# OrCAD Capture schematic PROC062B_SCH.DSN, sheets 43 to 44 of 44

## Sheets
43 43. OVER VOLTAGE PROTECTION CKT: size C; title: OVER VOLTAGE  PROTECTION CKT AND TEST AUTOMATION POWER
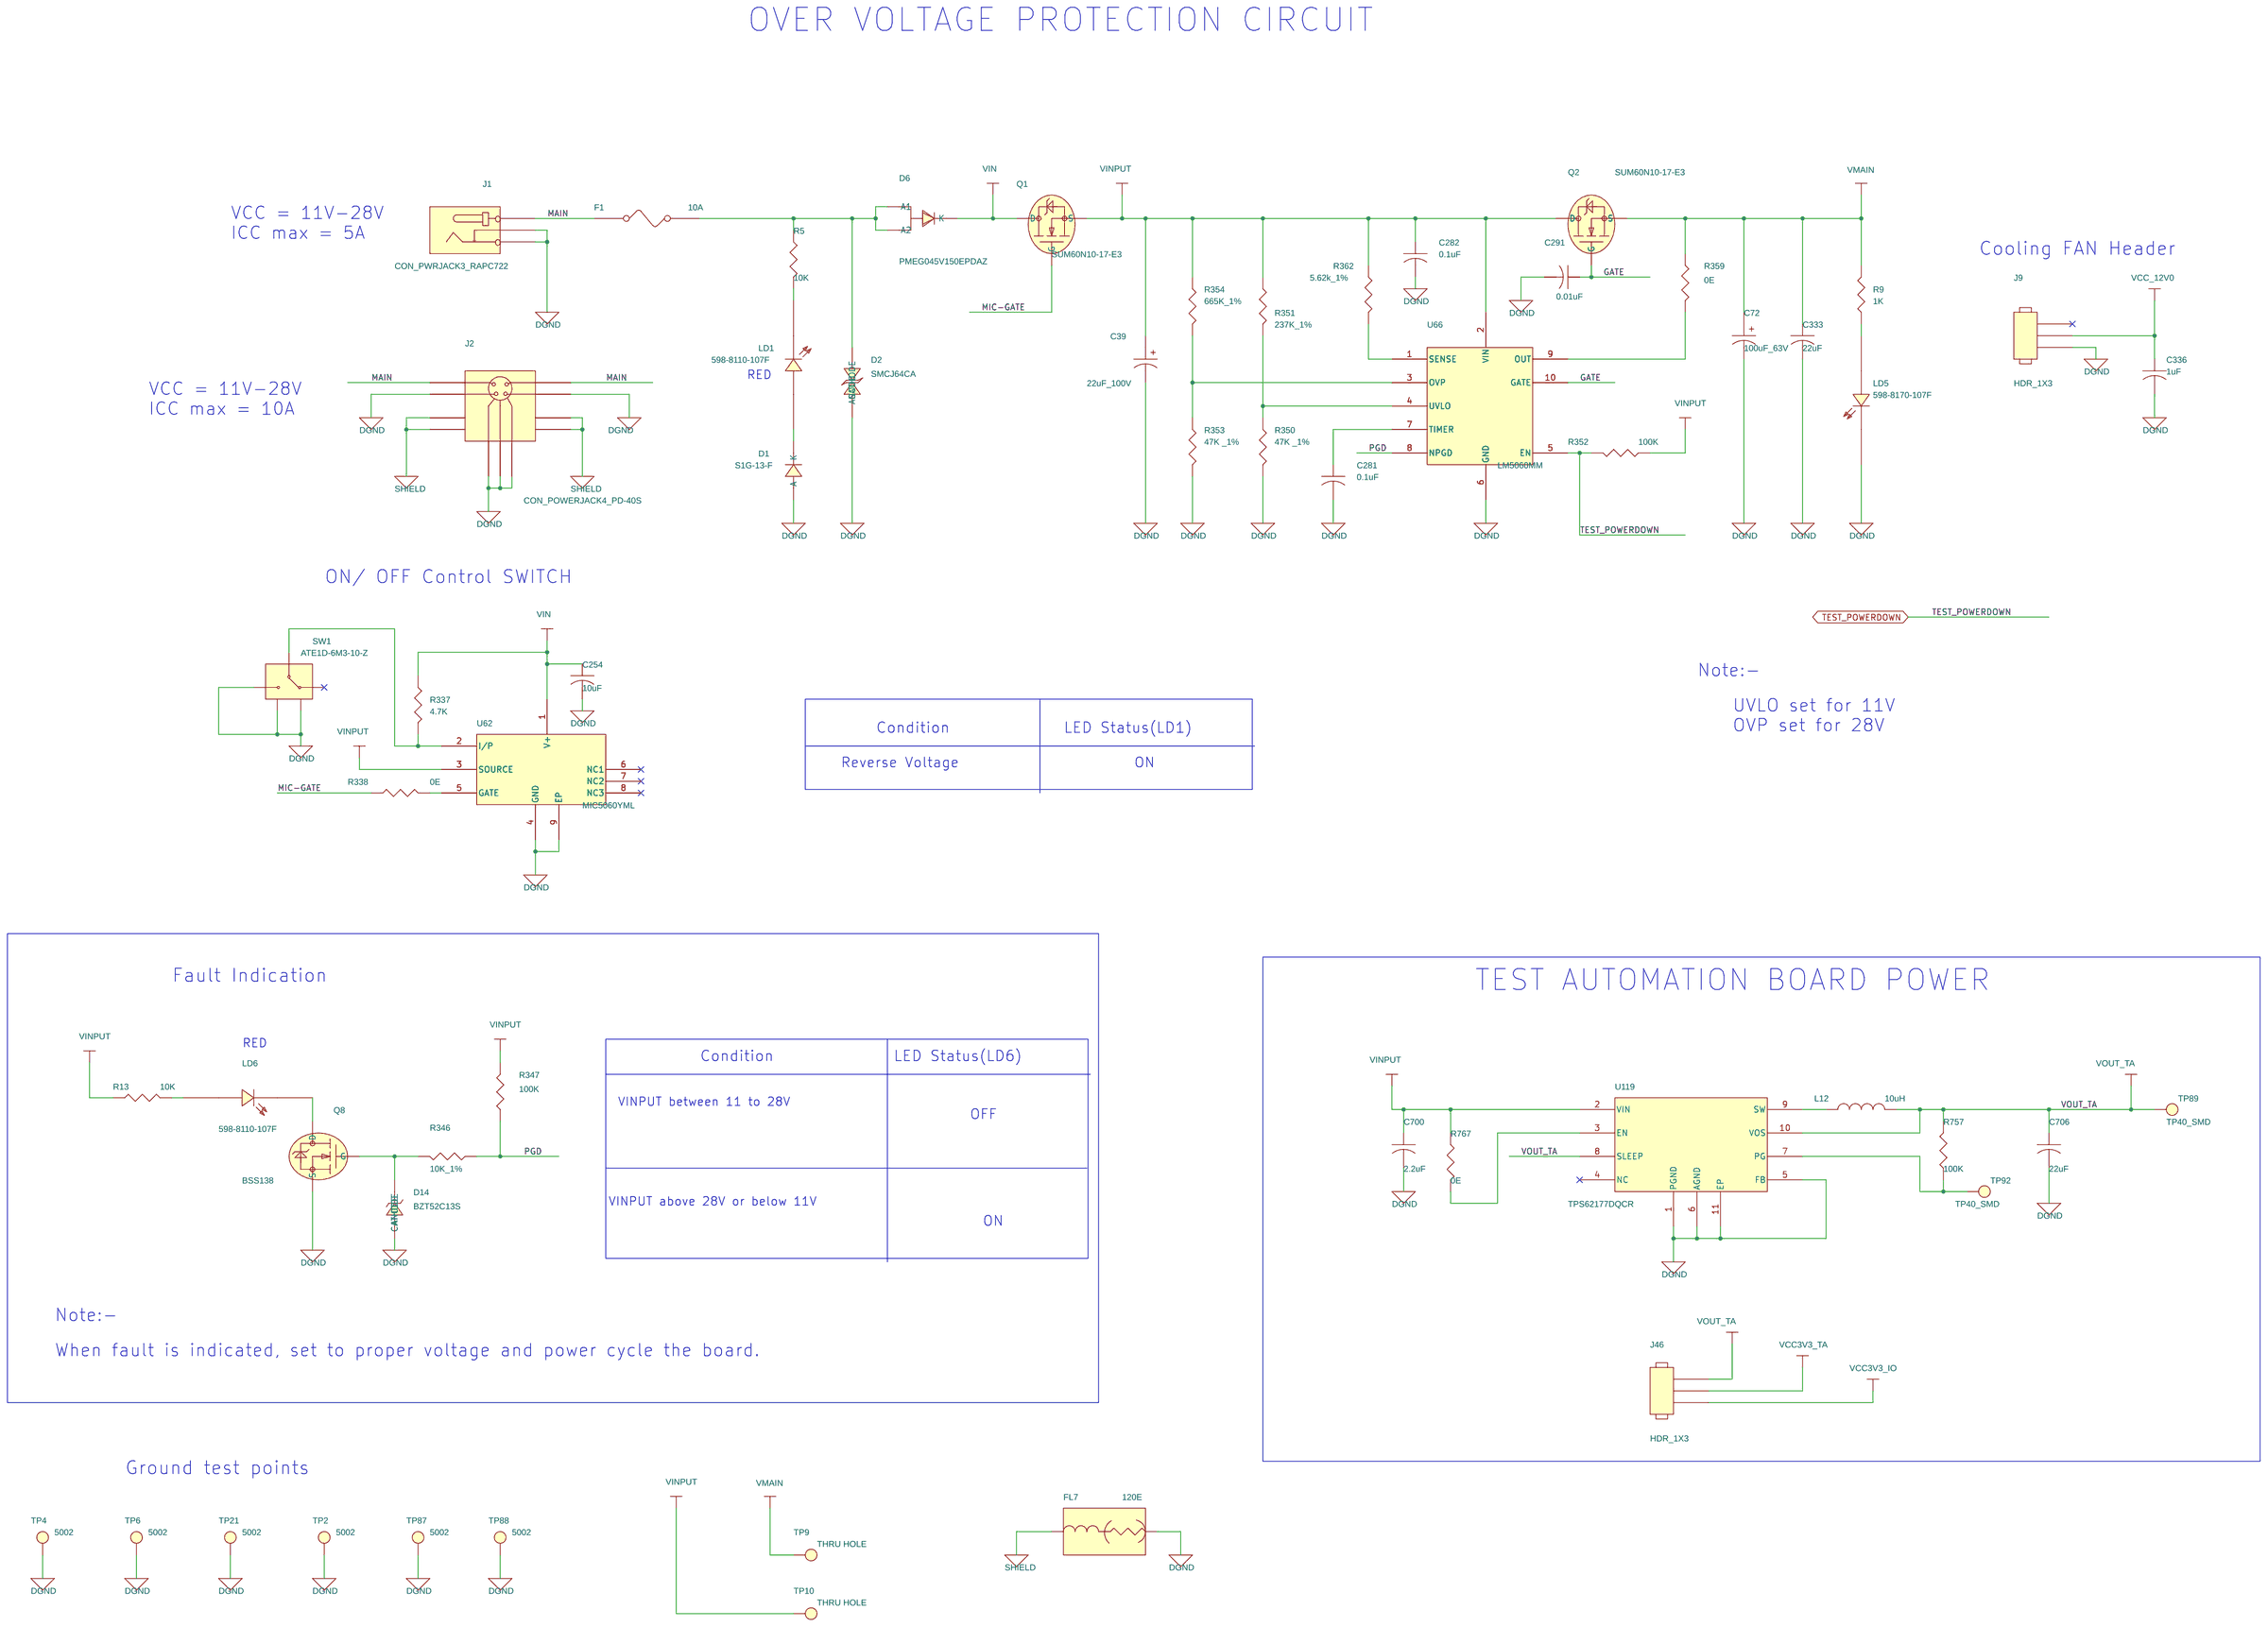
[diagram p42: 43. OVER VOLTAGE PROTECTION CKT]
44 35. CSI,GPMC/DSS INTERFACE: size C; title: CSI,GPMC/DSS INTERFACE
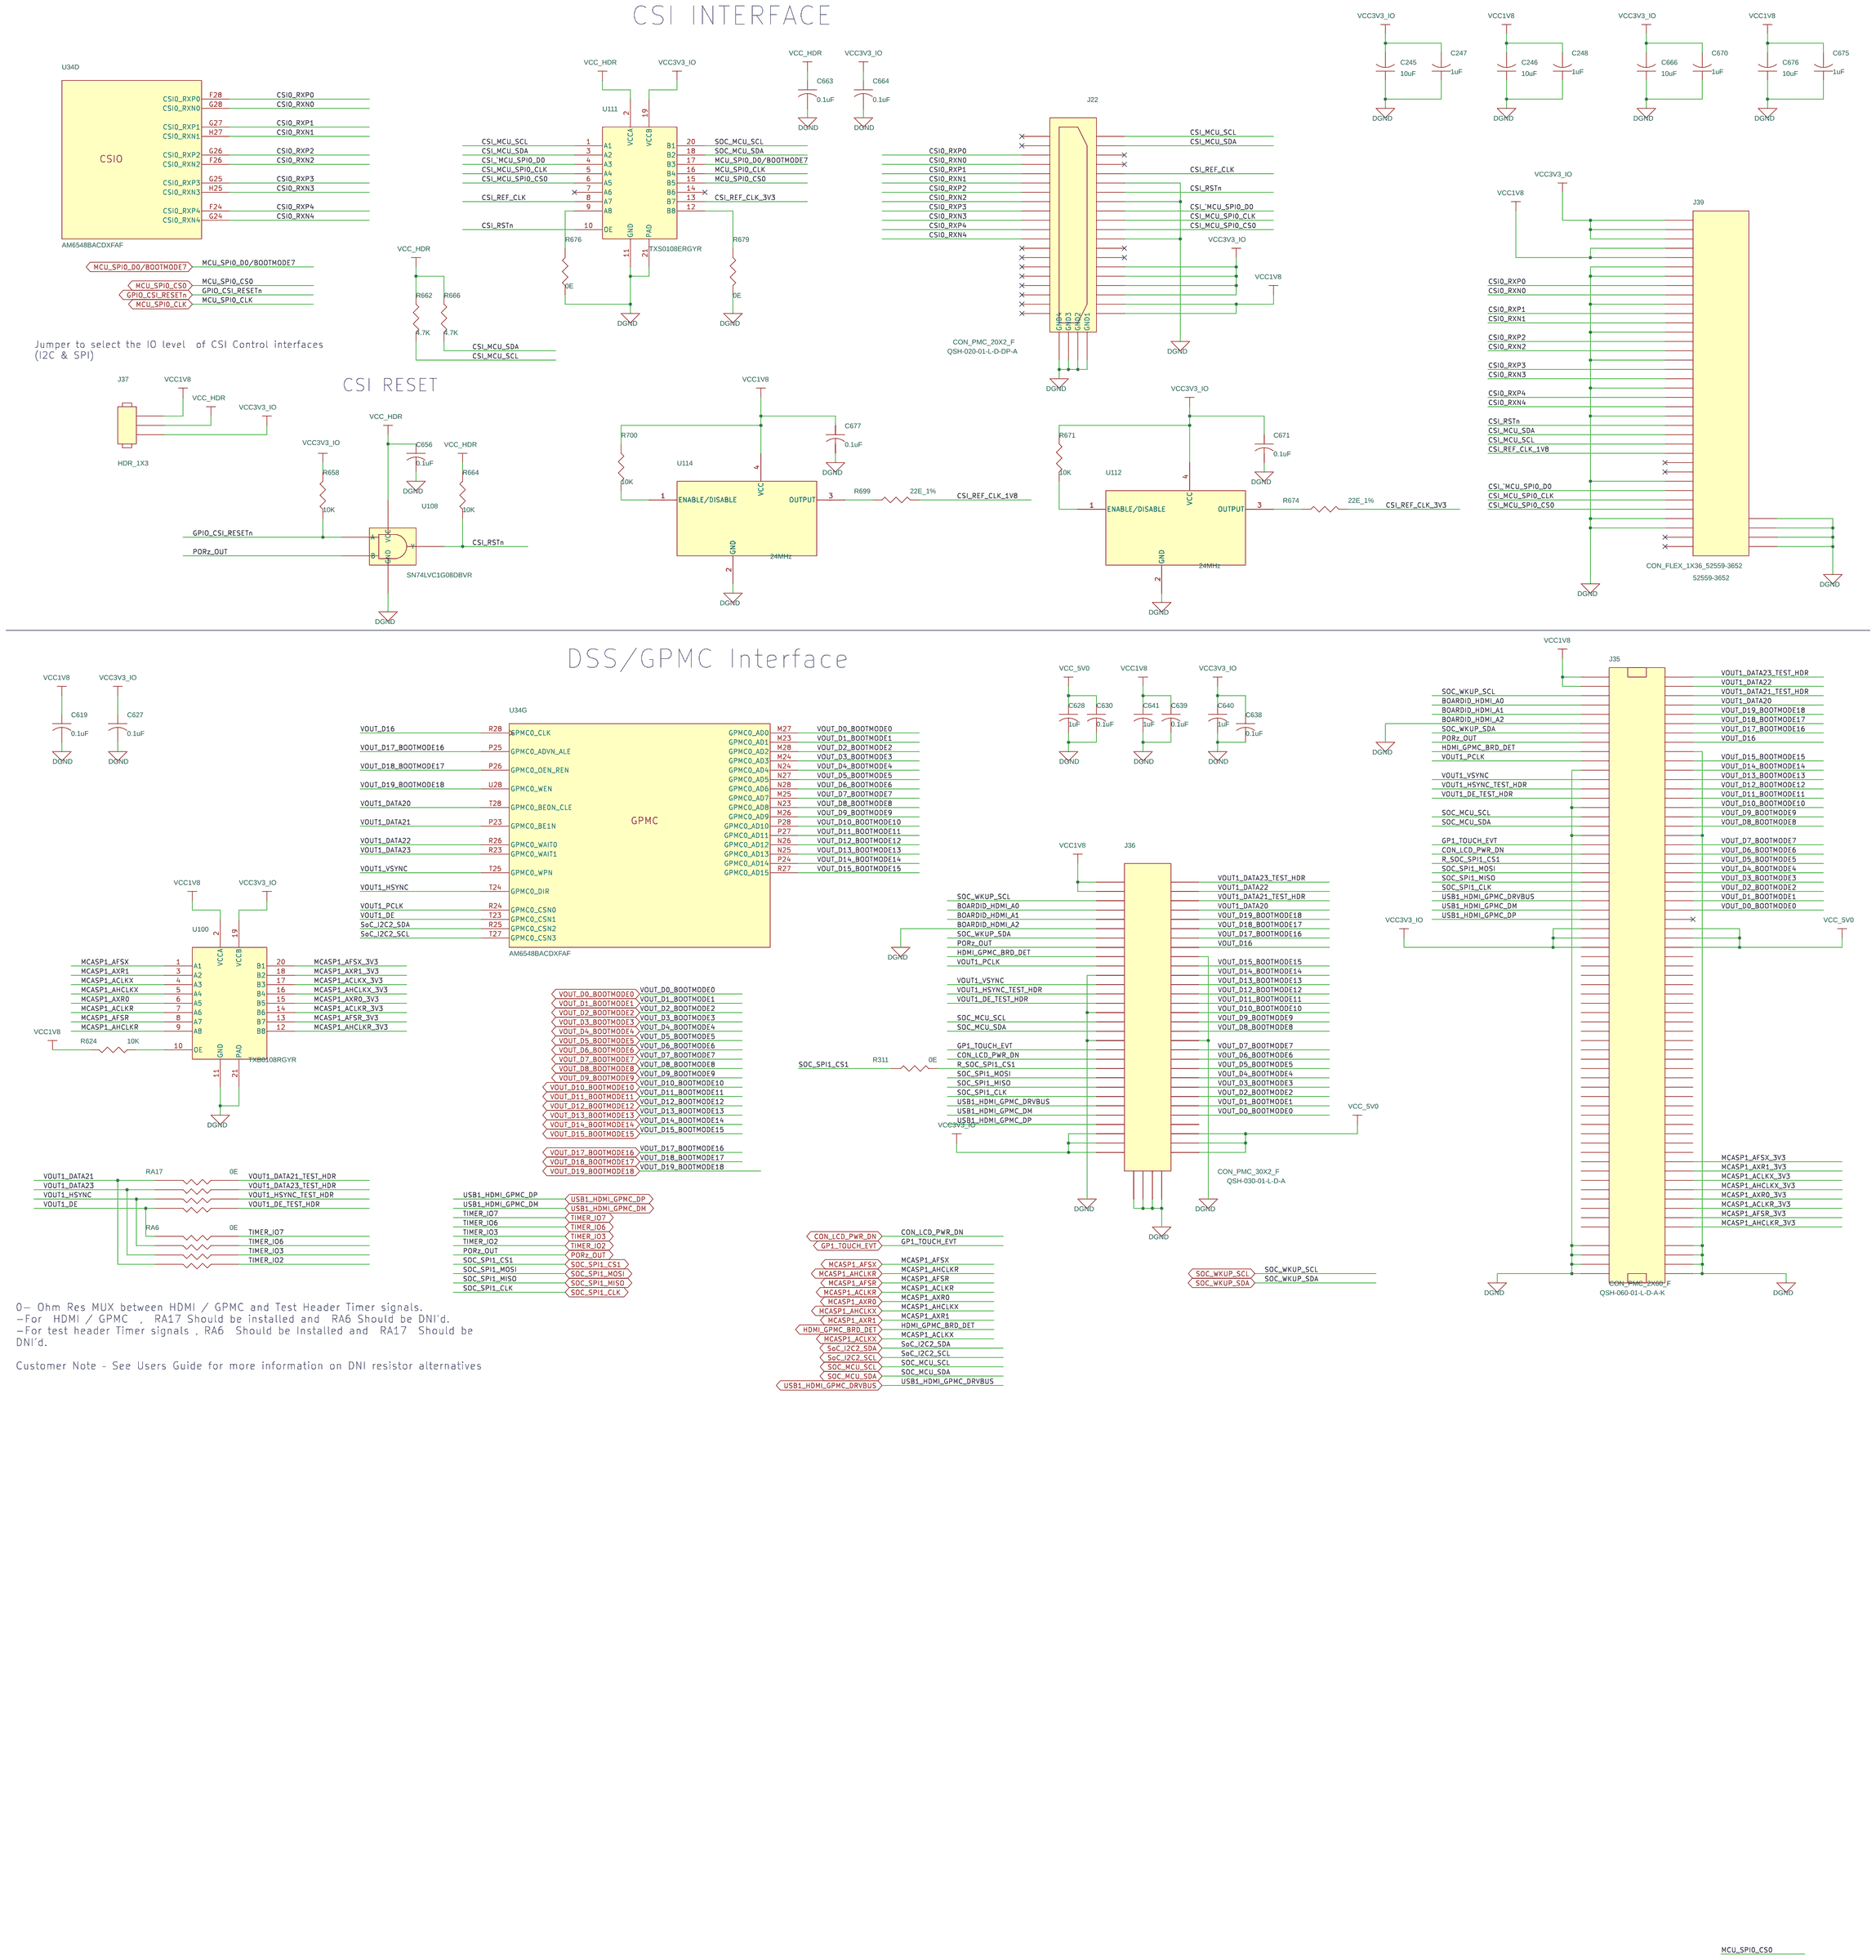
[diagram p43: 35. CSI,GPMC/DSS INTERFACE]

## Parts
sheet 16. DDR4 ECC & TERMINATIONS
U34  AM6548BACDXFAF  [BGA784_31-49_910X910_1-7]  (sections A,B,C,D,E,F,G,H,I,J,K,L,M,N,O,P,Q,R,S)
sheet 35. CSI,GPMC/DSS INTERFACE
C245  10uF  [CAP0603_1]
C246  10uF  [CAP0603_1]
C247  1uF  [CAP0402_0-75]
C248  1uF  [CAP0402_0-75]
C619  0.1uF  [CAP0201_0-5]
C627  0.1uF  [CAP0201_0-5]
C628  1uF  [CAP0402_0-75]
C630  0.1uF  [CAP0201_0-5]
C638  0.1uF  [CAP0201_0-5]
C639  0.1uF  [CAP0201_0-5]
C640  1uF  [CAP0402_0-75]
C641  1uF  [CAP0402_0-75]
C656  0.1uF  [CAP0201_0-5]
C663  0.1uF  [CAP0201_0-5]
C664  0.1uF  [CAP0201_0-5]
C666  10uF  [CAP0603_1]
C670  1uF  [CAP0402_0-75]
C671  0.1uF  [CAP0201_0-5]
C675  1uF  [CAP0402_0-75]
C676  10uF  [CAP0603_1]
C677  0.1uF  [CAP0201_0-5]
J22  CON_PMC_20X2_F  [CON_PMC20X2_QSH-D-DP_S_S_S]
J35  CON_PMC_2X60_F  [CON_PMC60X2_HQCD-060_S_S_S_3-3]
J36  CON_PMC_30X2_F  [CON_PMC30X2_QSH-030-01-L_S_S_S]
J37  HDR_1X3  [HDR_3X1_100_S_T]
J39  CON_FLEX_1X36_52559-3652  [CON_FLEX1X36_52559-36_S_S_S_5-3]
R311  0E  [RES0402_0-5]
R624  10K  [RES0402_0-5]
R658  10K  [RES0402_0-5]
R662  4.7K  [RES0402]
R664  10K  [RES0402_0-5]
R666  4.7K  [RES0402]
R671  10K  [RES0402_0-5]
R674  22E_1%  [RES0402]
R676  0E  [RES0402_0-5]
R679  0E  [RES0402_0-5]
R699  22E_1%  [RES0402]
R700  10K  [RES0402_0-5]
RA6  0E  [RESA_EXBN8V_0402-4_0-6]
RA17  0E  [RESA_EXBN8V_0402-4_0-6]
U100  TXB0108RGYR  [QFN20_19-68_185X145_1]
U108  SN74LVC1G08DBVR  [SOT23-5]
U111  TXS0108ERGYR  [QFN20_19-68_185X145_1]
U112  24MHz  [OSC4_KC2520B_100X80_SMD]
U114  24MHz  [OSC4_KC2520B_100X80_SMD]
sheet 43. OVER VOLTAGE PROTECTION CKT
C39  22uF_100V  [CAPAE_GCASE]
C72  100uF_63V  [CAPAE_CASE103103_11]
C254  10uF  [CAP1206_2]
C281  0.1uF  [CAP0603_1]
C282  0.1uF  [CAP0603_1]
C291  0.01uF  [CAP0201_0-5]
C333  22uF  [CAP7563_4]
C336  1uF  [CAP0603_1]
C700  2.2uF  [CAP1206_2]
C706  22uF  [CAP1206_2]
D1  S1G-13-F  [DIO_SMA]
D2  SMCJ64CA  [DIO_SMC]
D6  PMEG045V150EPDAZ  [CFP15_PMEG045V150EPD_0-9]
D14  BZT52C13S  [DIO_SOD323]
F1  10A  [FUSE_397_410X110_SMD_2-9]
FL7  120E  [EMIFIL_BLM15A_0402_0-6]
J1  CON_PWRJACK3_RAPC722  [CON_PWRJACK3_RAPC722_P_R_T]
J2  CON_POWERJACK4_PD-40S  [CON_POWERJACK4_PD-40S_S_R_T_15]
J9  HDR_1X3  [HDR_1X3_440054-3_S_T_6-4]
J46  HDR_1X3  [HDR_3X1_100_S_T]
L12  10uH  [IND_LPS4018-MR_160X160_SMD_1-8]
LD1  598-8110-107F  [LED_0805]
LD5  598-8170-107F  [LED_0805_0-7]
LD6  598-8110-107F  [LED_0805]
Q1  SUM60N10-17-E3  [D2PAK-3]
Q2  SUM60N10-17-E3  [D2PAK-3]
Q8  BSS138  [TO_SOT23-123]
R5  10K  [RES1206]
R9  1K  [RES0201]
R13  10K  [RES1206]
R337  4.7K  [RES0402]
R338  0E  [RES0402_0-5]
R346  10K_1%  [RES0402_0-5]
R347  100K  [RES0402_0-5]
R350  47K _1%  [RES0402_0-5]
R351  237K_1%  [RES0402]
R352  100K  [RES0402_0-5]
R353  47K _1%  [RES0402_0-5]
R354  665K_1%  [RES0603_0-5]
R359  0E  [RES0402_0-5]
R362  5.62k_1%  [RES0603]
R757  100K  [RES0402_0-5]
R767  0E  [RES0402_0-5]
SW1  ATE1D-6M3-10-Z  [SW3_ATE1F-6M3_370X710_TH_5-6]
TP2  5002  [TP_CIR67D40_TH_4-6]
TP4  5002  [TP_CIR67D40_TH_4-6]
TP6  5002  [TP_CIR67D40_TH_4-6]
TP9  THRU HOLE  [TP_40X65]
TP10  THRU HOLE  [TP_40X65]
TP21  5002  [TP_CIR67D40_TH_4-6]
TP87  5002  [TP_CIR67D40_TH_4-6]
TP88  5002  [TP_CIR67D40_TH_4-6]
TP89  TP40_SMD  [TP40_SMD]
TP92  TP40_SMD  [TP40_SMD]
U62  MIC5060YML  [DFN8_25-59_120X120_1]
U66  LM5060MM  [MSOP10_19-68_120X120]
U119  TPS62177DQCR  [WSON10_19-68_80X120_0-8]

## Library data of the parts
U34 = AM654X_BGA784: IC AM65X MICRO CONTROLLER UNIT BGA784; Chkd/date: ALVY/010721; Crtd /date: MANIRAJA/010721; Custom_Duty: 15%; Customs_HS_Code: 85423100; Distributor_name: NA; Distributor_part_number: NA; Footprint Path: Y:\MIS_DATABASE\Library\ALTIUM_TOOL\PCB_FOOTPRINTS\Altium_Footprint_Lib.PcbLib; Height: 1.63MM; Library Path: Y:\MIS_DATABASE\Library\ALTIUM_TOOL\SCHEMATICS_PARTS\MS_MICROCONTROLLER_Library.schlib; Mfr_name: TEXAS INSTRUMENTS; Mistral Part No: 141221070001; Package: BGA784; Part_type: ICS\DIGITAL\MICROCONTROLLER; Project: TI_AM65X_CP; RoHS: NA; Temperature: NA; Tolerance: NA; Voltage: NA; Wattage: NA; Weight: NA; Datasheet: Y:\MIS_DATABASE\DATASHEETS\ICS\DIGITAL\MICROCONTROLLER\MAXWELLM4.PDF
C245 C246 C666 C676 = CAP: CAP CERAMIC 10uF 10V 10% X5R 0603; Chkd/date: MANIRAJA/230118; Crtd /date: MANIRAJA/230118; Custom_Duty: 15%; Customs_HS_Code: 85322990; Distributor_name: DIGIKEY; Distributor_part_number: 478-10766-1-ND; Height: 0.94MM; Mfr_name: AVX CORPORATION; Mfr_part_number: 0603ZD106KAT2A; Mistral Part No: 120010080001-R; Package: 0603; Part_type: CAPACITORS\CERAMIC; Project: TI_MAXIE_CPB; RoHS: RoHS; Temperature: -55°C+85°C; Tolerance: 10%; Voltage: 10V; Wattage: NA; Weight: 2mg; Datasheet: Y:\MIS_DATABASE\DATASHEETS\CAPACITORS\AVX_MLC.PDF
C247 C248 C628 C640 C641 C670 C675 = CAP: CAP CERAMIC 1uF 16V 20% X5R 0402; Chkd/date: MANIRAJA/150218; Crtd /date: ALVY/150218; Custom_Duty: 15%; Customs_HS_Code: 85322990; Distributor_name: DIGIKEY; Distributor_part_number: 587-5514-1-ND; Footprint Path: Y:\MIS_DATABASE\Library\ALTIUM_TOOL\PCB_FOOTPRINTS\Altium_Footprint_Lib.PcbLib; Height: 0.55MM; Library Path: Y:\MIS_DATABASE\Library\ALTIUM_TOOL\SCHEMATICS_PARTS\MS_DISCRETE_Library.schlib; Mfr_name: TAIYO YUDEN; Mfr_part_number: EMK105BJ105MV-F; Mistral Part No: 120018020006-R; Package: 0402; Part_type: CAPACITORS\CERAMIC; Project: TI_MAXIE_CPB; RoHS: RoHS; Temperature: -55°C+85°C; Tolerance: 20%; Voltage: 16V; Wattage: NA; Weight: 0.65mg; Datasheet: Y:\MIS_DATABASE\DATASHEETS\CAPACITORS\EMK105BJ105MV-F.PDF
C619 C627 C630 C638 C639 C656 C663 C664 C671 C677 = CAP: CAP CERAMIC 0.1uF 16V 10% X5R 0201; Chkd/date: MANIRAJA/120218; Crtd /date: MANIRAJA/120218; Custom_Duty: 15%; Customs_HS_Code: 85322990; Distributor_name: DIGIKEY; Distributor_part_number: 490-16742-1-ND; Height: 0.33MM; Mfr_name: MURATA; Mfr_part_number: GRM033R61C104KE84J; Mistral Part No: 120009030072-R; Package: 0201; Part_type: CAPACITORS\CERAMIC; Project: TI_MAXIE_CPB; RoHS: RoHS; Temperature: -55°C+85°C; Tolerance: 10%; Voltage: 16V; Wattage: NA; Weight: 0.33mg; Datasheet: Y:\MIS_DATABASE\DATASHEETS\CAPACITORS\GRM033R61C104KE84.PDF
J22 = CON_PMC_20X2_F: CON PMC 20X2 0.50MM PITCH FEMALE ST SMD; Chkd/date: USMAN/021214; Crtd /date: CHAITHANYA/031111; Custom_Duty: 24%; Customs_HS_Code: 85369090; Distributor_name: DIGIKEY; Distributor_part_number: QSH-020-01-L-D-DP-A-ND; Height: 3.25MM; Mfr_name: SAMTEC; Mfr_part_number: QSH-020-01-L-D-DP-A; Mistral Part No: 150011110006-R; Package: SMD; Part_type: CONNECTOR\PMC; Project: LLTR; RoHS: RoHS; Temperature: -55°C+125°C; Tolerance: NA; Voltage: NA; Wattage: NA; Weight: NA; Datasheet: Y:\MIS_DATABASE\DATASHEETS\CONNECTORS\QSH-SERIES.PDF
J35 = CON_PMC_60X2_HQCD: CON PMC 2X60 0.50MM PITCH FEMALE ST SMD; Chkd/date: MANIRAJA/230817; Crtd /date: MUDDU/020610; Custom_Duty: 24%; Customs_HS_Code: 85369090; Distributor_name: DIGIKEY; Distributor_part_number: SAM10652-ND; Height: 3.25MM; Mfr_name: SAMTEC; Mfr_part_number: QSH-060-01-L-D-A-K; Mistral Part No: 150010060004-R; Package: SMD; Part_type: CONNECTOR\PMC; Project: CENTAURUS; RoHS: RoHS; Temperature: -55°C+125°C; Tolerance: NA; Voltage: NA; Wattage: NA; Weight: NA; Datasheet: Y:\MIS_DATABASE\DATASHEETS\CONNECTORS\QSH.PDF
J36 = CON_PMC_30X2_F: CON PMC 30X2 0.50MM PITCH FEMALE ST SMD; Chkd/date: MAZHAR/180208; Crtd /date: USMAN/051108; Custom_Duty: 24%; Customs_HS_Code: 85369090; Height: 3.25MM; Mfr_name: SAMTEC; Mfr_part_number: QSH-030-01-L-D-A; Mistral Part No: 150009030606; Package: SMD; Part_type: CONNECTOR\PMC; Project: KHAN_HSST; Datasheet: Y:\MIS_DATABASE\DATASHEETS\CONNECTORS\QSH.PDF
J37 J46 = HEADER_3X1: HDR 1X3 2.54MM PITCH ST TH; Chkd/date: VASANTHA/290616; Crtd /date: VASANTHA/290616; Custom_Duty: 15%; Customs_HS_Code: 85322990; Distributor_name: DIGIKEY; Distributor_part_number: 609-3471-ND; Height: 8.58MM; Mfr_name: FCI; Mfr_part_number: 68001-403HLF; Mistral Part No: 150016060025-R; Package: THRU-HOLE; Part_type: CONNECTOR\HEADERS; Project: IKEYP; RoHS: RoHS; Temperature: -40°C+105°C; Tolerance: NA; Voltage: NA; Wattage: NA; Weight: NA; Datasheet: Y:\MIS_DATABASE\DATASHEETS\CONNECTORS\68000.PDF
J39 = CON_FLEX_36X1_52559-3652: CON FPC 1X36 0.50MM PITCH ST SMD; Chkd/date: MANIRAJA/060917; Crtd /date: MANIRAJA/060917; Custom_Duty: 24%; Customs_HS_Code: 85369090; Distributor_name: DIGIKEY; Distributor_part_number: WM7988CT-ND; Height: 5.30MM; Mfr_name: MOLEX; Mfr_part_number: 52559-3652; Mistral Part No: 150017090006-R; Package: SMD; Part_type: CONNECTOR\FPC; Project: TI_SVB_MAXWELL_DUT; RoHS: RoHS; Temperature: -40°C+85°C; Tolerance: NA; Voltage: NA; Wattage: NA; Weight: 429.23mg; Datasheet: Y:\MIS_DATABASE\DATASHEETS\CONNECTORS\52559.PDF
R311 R338 R359 R676 R679 R767 = RESISTOR: RES 0E 1/16W 0402; Chkd/date: VASANTHA/201216; Crtd /date: MUDDU/190810; Custom_Duty: 15%; Customs_HS_Code: 85332119; Distributor_name: DIGIKEY; Distributor_part_number: 541-0.0JCT-ND; Footprint Path: Y:\MIS_DATABASE\Library\ALTIUM_TOOL\PCB_FOOTPRINTS\Altium_Footprint_Lib.PcbLib; Height: 0.40MM; Library Path: Y:\MIS_DATABASE\Library\ALTIUM_TOOL\SCHEMATICS_PARTS\MS_DISCRETE_Library.schlib; Mfr_name: VISHAY; Mfr_part_number: CRCW04020000Z0ED; Mistral Part No: 110010080019-P; Package: 0402; Part_type: RESISTORS\FIXED; Project: PB_BUGBASE; RoHS: Pb-Free; Temperature: -55°C+155°C; Tolerance: NA; Voltage: NA; Wattage: 1/16W; Weight: 0.65g/1000pcs; Datasheet: Y:\MIS_DATABASE\DATASHEETS\RESISTORS\CRCW0603.PDF
R624 R658 R664 R671 R700 = RESISTOR: RES 10K 1/16W 5% 0402; Chkd/date: VASANTHA/061216; Crtd /date: MAZHAR/230805; Custom_Duty: 15%; Customs_HS_Code: 85332119; Distributor_name: DIGIKEY; Distributor_part_number: 311-10KJRCT-ND; Footprint Path: Y:\MIS_DATABASE\Library\ALTIUM_TOOL\PCB_FOOTPRINTS\Altium_Footprint_Lib.PcbLib; Height: 0.40MM; Library Path: Y:\MIS_DATABASE\Library\ALTIUM_TOOL\SCHEMATICS_PARTS\MS_DISCRETE_Library.schlib; Mfr_name: YAGEO AMERICA; Mfr_part_number: RC0402JR-0710KL; Mistral Part No: 110009030208-R; Package: 0402; Part_type: RESISTORS\FIXED; Project: HSE; RoHS: Pb-Free; Temperature: -55°C+155°C; Tolerance: 5%; Voltage: NA; Wattage: 1/16W; Weight: 0.65mg; Datasheet: Y:\MIS_DATABASE\DATASHEETS\RESISTORS\YAGEO-RC0402.PDF
R337 R662 R666 = RESISTOR: RES 4.7K 1/16W 5% 0402; Chkd/date: VASANTHA/130516; Crtd /date: VASANTHA/130516; Custom_Duty: 15%; Customs_HS_Code: 85332119; Distributor_name: DIGIKEY; Distributor_part_number: 311-4.7KJRCT-ND; Height: 0.55MM; Mfr_name: YAGEO AMERICA; Mfr_part_number: RC0402JR-074K7L; Mistral Part No: 110009030792-R; Package: 0402; Part_type: RESISTORS\FIXED; Project: TMDXCSK368; RoHS: RoHS; Temperature: -55°C+155°C; Tolerance: 5%; Voltage: NA; Wattage: 1/16W; Weight: NA; Datasheet: Y:\MIS_DATABASE\DATASHEETS\RESISTORS\YAGEO-RC0402.PDF
R674 R699 = RESISTOR: RES 22E 1/16W 1% 0402; Alternate_mfr_name_A: VISHAY; Alternate_mfr_part_number_A: CRCW040222R0FKED; Chkd/date: SUHAS/290910; Crtd /date: MAZHAR/090909; Cust_part_number: 4700-80047E; Custom_Duty: 15%; Customs_HS_Code: 85332119; Distributor_name: DIGIKEY; Distributor_name_A: DIGIKEY; Distributor_part_number: 311-22.0LRCT-ND; Distributor_part_number_A: 541-22.0LCT-ND; Height: 0.40MM; Mfr_name: YAGEO AMERICA; Mfr_part_number: RC0402FR-0722RL; Mistral Part No: 110009090004-P; Package: 0402; Part_type: RESISTORS\FIXED; Project: VMEFMCD; Remarks: In alternate datasheet it is RoHS COMPLIANT. Y:\MIS_DATABASE\DATASHEETS\RESISTORS\CRCW0402.PDF; RoHS: Pb-Free; SIGNAL_MODEL: RESISTOR_RES0402_22E_22E; Temperature: -55°C+155°C; Tolerance: 1%; Voltage: 50V; Wattage: 1/16W; Weight: 0.8g/1000pcs; Datasheet: Y:\MIS_DATABASE\DATASHEETS\RESISTORS\YAGEO-RC0402.PDF
RA6 RA17 = RESARR_ISO4: RES ARRAY 0E 31mW 0402-4; Chkd/date: MANIRAJA/161017; Crtd /date: USMAN/190209; Distributor_name: DIGIKEY; Distributor_part_number: Y10000CT-ND; Height: 0.55MM; Mfr_name: PANASONIC-ECG; Mfr_part_number: EXB-N8VR000X; Mistral Part No: 110009030002-R; Package: 0402-4; Part_type: RESISTORS\ARRAY; Project: AXON; RoHS: RoHS; Temperature: -55°C+125°C; Tolerance: NA; Voltage: NA; Wattage: 31mW; Weight: 3mg; Datasheet: Y:\MIS_DATABASE\DATASHEETS\RESISTORS\EXB-X.PDF
U100 = TXB0108RGYR_VQFN20: IC 8-BIT TRANSLATOR 15KV ESD VQFN20; Chkd/date: VASANTHA/221216; Crtd /date: MUDDU/190510; Custom_Duty: 15%; Customs_HS_Code: 85423100; Distributor_name: DIGIKEY; Distributor_part_number: 296-21528-1-ND; Height: 1.00MM; Mfr_name: TEXAS INSTRUMENTS; Mistral Part No: 141010050005-R; Package: VQFN20; Part_type: ICS\INTERFACE; Project: SHIVA; RoHS: Sb/ Br FREE; Temperature: -40°C+85°C; Tolerance: NA; Voltage: NA; Wattage: NA; Weight: 43mg; Datasheet: Y:\MIS_DATABASE\DATASHEETS\ICS\INTERFACE\TXB0108RGYR.PDF
U108 = SN74LVC1G08DBVR_SOT23-5: IC SINGLE 2-INPUT POSITIVE AND GATE SOT23-5; Chkd/date: SHREESHAIL/270906; Crtd /date: MAZHAR/270906; Custom_Duty: 15%; Customs_HS_Code: 85423100; Distributor_name: DIGIKEY; Distributor_part_number: 296-11601-1-ND; Height: 1.45MM; Mfr_name: TEXAS INSTRUMENTS; Mistral Part No: 141009030228-R; Part_type: ICS\DIGITAL\GATES; Project: SVDO_RMB_MMA; RoHS: Sb/ Br FREE; Datasheet: Y:\MIS_DATABASE\DATASHEETS\ICS\DIGITAL\GATES\SN74LVC1G08.PDF
U111 = TXS0108ERGYR_QFN20: IC TRANSLATOR BIDIRECTIONAL VOLTAGE-LEVEL 8BIT QFN20; Chkd/date: VASANTHA/060117; Crtd /date: BAVISH/280411; Custom_Duty: 15%; Customs_HS_Code: 85423100; Distributor_name: DIGIKEY; Distributor_part_number: 296-24806-1-ND; Height: 1.00MM; Mfr_name: TEXAS INSTRUMENTS; Mistral Part No: 141011040019-R; Package: QFN20; Part_type: ICS\INTERFACE; Project: OMAPL1_PEC20; RoHS: RoHS; Temperature: -40°C+85°C; Tolerance: NA; Voltage: NA; Wattage: NA; Weight: 43mg; Datasheet: Y:\MIS_DATABASE\DATASHEETS\ICS\INTERFACE\TXS0108E.PDF
U112 U114 = OSC_KC2520B: OSC 24MHz 1.8V SMD; Chkd/date: NAVEED/080415; Crtd /date: JEBRAN/310315; Custom_Duty: 24%; Customs_HS_Code: 85437099; Distributor_name: DIGIKEY; Distributor_part_number: 1253-1244-1-ND; Height: 0.70MM; Mfr_name: KYOCERA; Mfr_part_number: KC2520B24.0000C1GE00; Mistral Part No: 130015030022-R; Package: SMD; Part_type: OSCILLATORS; Project: DLRL; RoHS: RoHS; Temperature: -40°C+85°C; Tolerance: NA; Voltage: NA; Wattage: NA; Weight: NA; Datasheet: Y:\MIS_DATABASE\DATASHEETS\MISC\CRY_OSC\KC2520B2.PDF
C39 = CAP_POL: CAP ELECTROLYTIC 22uF 100V 20% GCASE_103103; Chkd/date: USMAN/141211; Crtd /date: CHAITHANYA/131211; Custom_Duty: 15%; Customs_HS_Code: 85322990; Distributor_name: DIGIKEY; Distributor_part_number: PCE4250CT-ND; Height: 10.50MM; Mfr_name: PANASONIC-ECG; Mfr_part_number: EEE-HA2A220P; Mistral Part No: 120011120008-R; Package: GCASE_103103; Part_type: CAPACITORS\ELECTROLYTIC; Project: NA10NG; RoHS: RoHS; Temperature: -40°C+105°C; Tolerance: 20%; Voltage: 100V; Wattage: NA; Weight: NA; Datasheet: Y:\MIS_DATABASE\DATASHEETS\CAPACITORS\EEEHA-V-SERIES.PDF
C72 = CAP_POL: CAP ELECTROLYTIC 100uF 63V 20% CASE_103103; Chkd/date: MANIRAJA/120218; Crtd /date: MANIRAJA/120218; Custom_Duty: 15%; Customs_HS_Code: 85322990; Distributor_name: DIGIKEY; Distributor_part_number: 493-7453-1-ND; Height: 10.80MM; Mfr_name: NICHICON; Mfr_part_number: UUX1J101MNL1GS; Mistral Part No: 120018010018-R; Package: CASE_103103; Part_type: CAPACITORS\ELECTROLYTIC; Project: TI_MAXIE_CPB; RoHS: RoHS; Temperature: -55°C+105°C; Tolerance: 20%; Voltage: 63V; Wattage: NA; Weight: 1.21g; Datasheet: Y:\MIS_DATABASE\DATASHEETS\CAPACITORS\UUX-SER.PDF
C254 = CAP: CAP CERAMIC 10uF 50V 10% X5R 1206; Chkd/date: VASANTHA/190814; Crtd /date: BAVISH/230611; Custom_Duty: 15%; Customs_HS_Code: 85322990; Distributor_name: DIGIKEY; Distributor_part_number: 445-5998-1-ND; Footprint Path: Y:\MIS_DATABASE\Library\ALTIUM_TOOL\PCB_FOOTPRINTS\Altium_Footprint_Lib.PcbLib; Height: 1.90MM; Library Path: Y:\MIS_DATABASE\Library\ALTIUM_TOOL\SCHEMATICS_PARTS\MS_DISCRETE_Library.schlib; Mfr_name: TDK CORPORATION; Mfr_part_number: C3216X5R1H106K160AB; Mistral Part No: 120016030005-R; Package: 1206; Part_type: CAPACITORS\CERAMIC; Project: ITS-SINGAL_COND_CARD; RoHS: RoHS; Temperature: -55°C+85°C; Tolerance: 10%; Voltage: 50V; Wattage: NA; Weight: 16.2mg; Datasheet: Y:\MIS_DATABASE\DATASHEETS\CAPACITORS\TDK_C-SER-JUL17.PDF
C281 C282 = CAP: CAP CERAMIC 0.1uF 50V 20% X7R 0603; Chkd/date: MANIRAJA/240118; Crtd /date: MANIRAJA/240118; Custom_Duty: 15%; Customs_HS_Code: 85322990; Distributor_name: DIGIKEY; Distributor_part_number: 399-7845-1-ND; Height: 0.95MM; Mfr_name: KEMET; Mfr_part_number: C0603C104M5RACTU; Mistral Part No: 120018010021-R; Package: 0603; Part_type: CAPACITORS\CERAMIC; Project: TI_MAXIE_CPB; RoHS: RoHS; Temperature: -55°C+125°C; Tolerance: 20%; Voltage: 50V; Wattage: NA; Weight: 2mg; Datasheet: Y:\MIS_DATABASE\DATASHEETS\CAPACITORS\KEMET-X7R-SER.PDF
C291 = CAP: CAP CERAMIC 0.01uF 25V 10% X5R 0201; Chkd/date: MANIRAJA/230118; Crtd /date: MANIRAJA/230118; Custom_Duty: 15%; Customs_HS_Code: 85322990; Distributor_name: DIGIKEY; Distributor_part_number: GRM033R61E103KA12J-ND; Height: 0.33MM; Mfr_name: MURATA; Mfr_part_number: GRM033R61E103KA12J; Mistral Part No: 120018010007-R; Package: 0201; Part_type: CAPACITORS\CERAMIC; Project: TI_MAXIE_CPB; RoHS: RoHS; Temperature: -55°C+85°C; Tolerance: 10%; Voltage: 25V; Wattage: NA; Weight: 0.33mg; Datasheet: Y:\MIS_DATABASE\DATASHEETS\CAPACITORS\GRM033R61E103KA12.PDF
C333 = CAP: CAP CERAMIC 22uF 50V 20% X7R 7563; Chkd/date: MANIRAJA/121017; Crtd /date: MANIRAJA/121017; Custom_Duty: 15%; Customs_HS_Code: 85322990; Distributor_name: DIGIKEY; Distributor_part_number: 565-4700-1-ND; Height: 4.00MM; Mfr_name: NIPPON CHEMICON; Mfr_part_number: KTS500B226M76N0T00; Mistral Part No: 120017100007-R; Package: 7563; Part_type: CAPACITORS\CERAMIC; Project: TI_MAXIE_CPB; RoHS: RoHS; Temperature: -55°C+125°C; Tolerance: 20%; Voltage: 50V; Wattage: NA; Weight: NA; Datasheet: Y:\MIS_DATABASE\DATASHEETS\CAPACITORS\NTS-NTF-SER.PDF
C336 = CAP: CAP CERAMIC 1uF 25V 10% X5R 0603; Chkd/date: MANIRAJA/230118; Crtd /date: MANIRAJA/230118; Custom_Duty: 15%; Customs_HS_Code: 85322990; Distributor_name: DIGIKEY; Distributor_part_number: 478-5142-1-ND; Height: 0.94MM; Mfr_name: AVX CORPORATION; Mfr_part_number: 06033D105KAT2A; Mistral Part No: 120010080040-R; Package: 0603; Part_type: CAPACITORS\CERAMIC; Project: TI_MAXIE_CPB; RoHS: RoHS; Temperature: -55°C+85°C; Tolerance: 10%; Voltage: 25V; Wattage: NA; Weight: 2mg; Datasheet: Y:\MIS_DATABASE\DATASHEETS\CAPACITORS\AVX_MLC.PDF
C700 = CAP: CAP CERAMIC 2.2uF 50V 10% X7R AUTO 1206; Chkd/date: MAZHAR/290208; Crtd /date: USMAN/280208; Custom_Duty: 15%; Customs_HS_Code: 85322990; Distributor_name: DIGIKEY; Distributor_part_number: 490-4796-1-ND; Footprint Path: Y:\MIS_DATABASE\Library\ALTIUM_TOOL\PCB_FOOTPRINTS\Altium_Footprint_Lib.PcbLib; Height: 1.80MM; Library Path: Y:\MIS_DATABASE\Library\ALTIUM_TOOL\SCHEMATICS_PARTS\MS_DISCRETE_Library.schlib; Mfr_name: MURATA; Mfr_part_number: GCM31CR71H225KA55L; Mistral Part No: 120009030284-R; Package: 1206; Part_type: CAPACITORS\CERAMIC; Project: HS100RD; RoHS: RoHS; Temperature: -55°C+125°C; Tolerance: 10%; Voltage: 50V; Wattage: NA; Weight: 52mg; Datasheet: Y:\MIS_DATABASE\DATASHEETS\CAPACITORS\GCM31CR71H225KA55X.PDF
C706 = CAP: CAP CERAMIC 22uF 16V 20% X7R 1206; Chkd/date: VASANTHA/170117; Crtd /date: VASANTHA/170117; Custom_Duty: 15%; Customs_HS_Code: 85322990; Distributor_name: DIGIKEY; Distributor_part_number: 587-4319-1-ND; Height: 1.90MM; Mfr_name: TAIYO YUDEN; Mfr_part_number: EMK316BB7226ML-T; Mistral Part No: 120017010003-R; Package: 1206; Part_type: CAPACITORS\CERAMIC; Project: TRMM_SMART-M_PS; RoHS: RoHS; Temperature: -55°C+125°C; Tolerance: 20%; Voltage: 16V; Wattage: NA; Weight: 16.2mg; Datasheet: Y:\MIS_DATABASE\DATASHEETS\CAPACITORS\EMK316BB7226ML.PDF
D1 = DIODE: DIODE RECTIFIER 400V 1A SMA; Chkd/date: SUHAS/061010; Crtd /date: USMAN/220808; Custom_Duty: 15%; Customs_HS_Code: 85412900; Distributor_name: DIGIKEY; Distributor_part_number: S1G-FDICT-ND; Height: 2.30MM; Mfr_name: DIODES INC; Mistral Part No: 130009030153; Package: SMA; Part_type: DIODE\RECTIFIER; Project: CPB; Temperature: -65°C+150°C; Voltage: 400V; Weight: 0.0064g; Datasheet: Y:\MIS_DATABASE\DATASHEETS\DISCRETES\DIODES\S1.PDF
D2 = DIODE_TVS_DUAL: DIODE TVS BI-DIE 1500W 64V SMC; Chkd/date: VASANTHA/101015; Crtd /date: VASANTHA/101015; Custom_Duty: 15%; Customs_HS_Code: 85412900; Distributor_name: DIGIKEY; Distributor_part_number: SMCJ64CALFCT-ND; Height: 2.62MM; Mfr_name: LITTLE FUSE; Mistral Part No: 130015100009-R; Package: SMC; Part_type: DIODE\TVS; Project: GALILEO_EVM; RoHS: RoHS; Temperature: -55°C+150°C; Tolerance: NA; Voltage: 64V; Wattage: NA; Weight: NA; Datasheet: Y:\MIS_DATABASE\DATASHEETS\DISCRETES\DIODES\LTFUSE-SMCJ.PDF
D6 = DIODE_SCHOTTKY_POWERMITE-3: DIODE SCHOTTKY RECTIFIER 45V 15A CFP15 (SOT1289); Chkd/date: MANIRAJA/070220; Crtd /date: ALVY/070220; Custom_Duty: 15%; Customs_HS_Code: 85412900; Distributor_name: DIGIKEY; Distributor_part_number: 1727-1905-1-ND; Footprint Path: Y:\MIS_DATABASE\Library\ALTIUM_TOOL\PCB_FOOTPRINTS\Altium_Footprint_Lib.PcbLib; Height: 0.82MM; Library Path: Y:\MIS_DATABASE\Library\ALTIUM_TOOL\SCHEMATICS_PARTS\MS_DISCRETE_Library.schlib; Mfr_name: NEXPERIA; Mistral Part No: 130020020003-R; Package: CFP15; Part_type: DIODE\SCHOTTKY; Project: TI_MAXIE_CPB; RoHS: RoHS; Temperature: -55°C+175°C; Tolerance: NA; Voltage: NA; Wattage: NA; Weight: 87.3mg; Datasheet: Y:\MIS_DATABASE\DATASHEETS\DISCRETES\DIODES\PMEG045V150EPD.PDF
D14 = DIODE_ZENER: DIODE ZENER 13V 200mW SOD323; Chkd/date: MAZHAR/101210; Crtd /date: BAVISH/101210; Custom_Duty: 15%; Customs_HS_Code: 85412900; Distributor_name: DIGIKEY; Distributor_part_number: BZT52C13S-FDICT-ND; Height: 1.05MM; Mfr_name: DIODES INC; Mfr_part_number: BZT52C13S-7-F; Mistral Part No: 130010120013-R; Package: SOD323; Part_type: DIODE\ZENER; Project: IEMS; RoHS: RoHS; Temperature: -65°C+150°C; Tolerance: NA; Voltage: NA; Wattage: 200mW; Weight: 0.004g; Datasheet: Y:\MIS_DATABASE\DATASHEETS\DISCRETES\DIODES\BZT52C.PDF
F1 = FUSE: FUSE 10A 60V FAST SMD; Chkd/date: RAGESH/151010; Crtd /date: MAZHAR/220907; Distributor_name: DIGIKEY; Distributor_part_number: TR2/1025FA10-R-ND; Height: 2.90MM; Mfr_name: COOPER BUSSMANN; Mfr_part_number: 1025FA10-R; Mistral Part No: 130009030821-R; Package: SMD; Part_type: MISC\FUSE; Project: SMART VIEW_NVR; RoHS: RoHS; Voltage: 60V; Datasheet: Y:\MIS_DATABASE\DATASHEETS\MISC\FUSE\1025FA-SER.PDF
FL7 = EMIFILTER_IND: FERRITE CHIP 120E 1.3A 0402; Chkd/date: VASANTHA/010117; Crtd /date: CHAITHANYA/150312; Custom_Duty: 24%; Customs_HS_Code: 85437099; Distributor_name: DIGIKEY; Distributor_part_number: 490-5203-1-ND; Footprint Path: Y:\MIS_DATABASE\Library\ALTIUM_TOOL\PCB_FOOTPRINTS\Altium_Footprint_Lib.PcbLib; Height: 0.55MM; Library Path: Y:\MIS_DATABASE\Library\ALTIUM_TOOL\SCHEMATICS_PARTS\MS_FILTER_Library.schlib; Mfr_name: MURATA; Mfr_part_number: BLM15PD121SN1; Mistral Part No: 130012030043-R; Package: 0402; Part_type: MISC\FILTER; Project: GEN_3-8; RoHS: RoHS; Temperature: -55°C+125°C; Tolerance: 25%; Voltage: NA; Wattage: NA; Weight: 0.65mg; Datasheet: Y:\MIS_DATABASE\DATASHEETS\DISCRETES\INDUCTORS\BLM18K-SERIES.PDF
J1 = CON_PWRJACK3_RAPC722: CON POWER JACK 3POS 5A 1.93MMPIN-DIA MALE RT TH; Chkd/date: MAZHAR/220311; Crtd /date: BAVISH/230211; Custom_Duty: 24%; Customs_HS_Code: 85369090; Distributor_name: DIGIKEY; Distributor_part_number: SC1313-ND; Height: 11.00MM; Mfr_name: SWITCHCRAFT; Mfr_part_number: RAPC722X; Mistral Part No: 150011020010-R; Package: THRU-HOLE; Part_type: CONNECTOR\JACK; Project: KENNEL; RoHS: RoHS; Temperature: NA; Tolerance: NA; Voltage: NA; Wattage: NA; Weight: SOIC8; Datasheet: Y:\MIS_DATABASE\DATASHEETS\CONNECTORS\RAPC722.PDF
J2 = CON_POWERJACK_PD-40S: CON POWER JACK 4POS FEMALE RT TH; Chkd/date: VASANTHA/140616; Crtd /date: VASANTHA/140616; Custom_Duty: 24%; Customs_HS_Code: 85369090; Distributor_name: DIGIKEY; Distributor_part_number: CP-7240-ND; Height: 15.00MM; Mfr_name: CUI INC; Mfr_part_number: PD-40S; Mistral Part No: 150016060015-R; Package: THRU-HOLE; Part_type: CONNECTOR\JACK; Project: NTR_GPSDO BOX CARD; RoHS: RoHS; Temperature: NA; Tolerance: NA; Voltage: NA; Wattage: NA; Weight: NA; Datasheet: Y:\MIS_DATABASE\DATASHEETS\CONNECTORS\PD-40S.PDF
J9 = HEADER_3X1: CON HDR 1X3 2.00MM PITCH ST TH; Chkd/date: MANIRAJA/261017; Crtd /date: MANIRAJA/261017; Custom_Duty: 24%; Customs_HS_Code: 85369090; Distributor_name: DIGIKEY; Distributor_part_number: A100035-ND; Height: 6.35MM; Mfr_name: TE CONNECTIVITY; Mfr_part_number: 440054-3; Mistral Part No: 150017100038-R; Package: THRU-HOLE; Part_type: CONNECTOR\HEADERS; Project: TI_MAXIE_CPB; RoHS: RoHS; Temperature: -25°C+85°C; Tolerance: NA; Voltage: NA; Wattage: NA; Weight: NA; Datasheet: Y:\MIS_DATABASE\DATASHEETS\CONNECTORS\440054XXX.PDF
L12 = INDUCTOR: IND POWER 10uH 1.25A 20% SMD; Chkd/date: MANIRAJA/190819; Crtd /date: MANIRAJA/190819; Custom_Duty: 15%; Customs_HS_Code: 85412900; Distributor_name: MOUSER; Distributor_part_number: 994-LPS4018-103MRC; Footprint Path: Y:\MIS_DATABASE\Library\ALTIUM_TOOL\PCB_FOOTPRINTS\Altium_Footprint_Lib.PcbLib; Height: 1.80MM; Library Path: Y:\MIS_DATABASE\Library\ALTIUM_TOOL\SCHEMATICS_PARTS\MS_DISCRETE_Library.schlib; Mfr_name: COILCRAFT; Mfr_part_number: LPS4018-103MRC; Mistral Part No: 130019080008-R; Package: SMD; Project: TI_J7_SVB-DUT; RoHS: RoHS; Temperature: -40°C+85°C; Tolerance: 20%; Voltage: NA; Wattage: NA; Weight: 100mg; Datasheet: Y:\MIS_DATABASE\DATASHEETS\DISCRETES\INDUCTORS\LPS4018-RB-SERIES.PDF
LD1 LD6 = LED_598-8170-107F: LED ALINGAP RED CLEAR 0805 SMD; Chkd/date: BALACHANDAR/160514; Crtd /date: SARANYA/070514; Custom_Duty: 24%; Customs_HS_Code: 85437099; Distributor_name: DIGIKEY; Distributor_part_number: 350-2038-1-ND; Height: 0.70MM; Mfr_name: DIALIGHT; Mistral Part No: 130014050069-R; Package: 0805; Part_type: OPTO\LED; Project: AEGIS GP BETA2; RoHS: RoHS; Temperature: NA; Tolerance: NA; Voltage: NA; Wattage: NA; Weight: NA; Datasheet: Y:\MIS_DATABASE\DATASHEETS\DISCRETES\LEDS\598-SER.PDF
LD5 = LED_598-8170-107F: LED ALINGAP GREEN CLEAR 0805; Chkd/date: MANIRAJA/230817; Crtd /date: SARANYA/070514; Custom_Duty: 24%; Customs_HS_Code: 85437099; Distributor_name: DIGIKEY; Distributor_part_number: 350-2044-1-ND; Height: 0.70MM; Mfr_name: DIALIGHT; Mistral Part No: 130014050065-R; Package: 0805; Part_type: OPTO\LED; Project: AEGIS GP BETA2; RoHS: RoHS; Temperature: -30°C+85°C; Tolerance: NA; Voltage: NA; Wattage: NA; Weight: NA; Datasheet: Y:\MIS_DATABASE\DATASHEETS\DISCRETES\LEDS\598-SER.PDF
Q1 Q2 = MOSFET_IRFZ24NS: IC POWER MOSFET N-CHANNEL D2PAK; Chkd/date: VASANTHA/101015; Crtd /date: VASANTHA/101015; Custom_Duty: 15%; Customs_HS_Code: 85423100; Distributor_name: DIGIKEY; Distributor_part_number: SUM60N10-17-E3CT-ND; Height: 4.82MM; Mfr_name: VISHAY; Mistral Part No: 142015100008-R; Package: D2PAK; Part_type: ICS\POWER\MOSFET; Project: GALILEO_EVM; RoHS: RoHS; Temperature: -55°C+175°C; Tolerance: NA; Voltage: 100V; Wattage: NA; Weight: NA; Datasheet: Y:\MIS_DATABASE\DATASHEETS\DISCRETES\TRANSISTORS_FETS\SUM60N10.PDF
Q8 = MOSFET_BSS138: IC MOSFET N-CHANNEL 50V 200mA SOT23-3; Chkd/date: SUHAS/191010; Crtd /date: USMAN/240709; Custom_Duty: 15%; Customs_HS_Code: 85423100; Distributor_name: DIGIKEY; Distributor_part_number: BSS138CT-ND; Height: 1.20MM; Mfr_name: DIODES INC; Mfr_part_number: BSS138-7-F; Mistral Part No: 142009070019-R; Package: SOT23-3; Part_type: ICS\POWER\MOSFET; Project: KHAN_MAIN; RoHS: RoHS; Temperature: -55°C+150°C; Voltage: 50V; Wattage: 300mW; Weight: 0.008g; Datasheet: Y:\MIS_DATABASE\DATASHEETS\DISCRETES\TRANSISTORS_FETS\BSS138.PDF
R5 R13 = RESISTOR: RES 10K 2/3W 5% 1206; Chkd/date: VASANTHA/101015; Crtd /date: VASANTHA/101015; Custom_Duty: 15%; Customs_HS_Code: 85332119; Distributor_name: DIGIKEY; Distributor_part_number: P10KALCT-ND; Height: 0.70MM; Mfr_name: PANASONIC; Mfr_part_number: ERJ-P08J103V; Mistral Part No: 110015090016-R; Package: 1206; Part_type: RESISTORS\FIXED; Project: GALILEO_EVM; RoHS: RoHS; Temperature: -55°C+155°C; Tolerance: 5%; Voltage: NA; Wattage: 2/3W; Weight: 10g/1000pcs; Datasheet: Y:\MIS_DATABASE\DATASHEETS\RESISTORS\ERJ_SERIES.PDF
R9 = RESISTOR: RES 1K 1/20W 5% 0201; Chkd/date: JEBRAN/110815; Crtd /date: JEBRAN/110815; Custom_Duty: 15%; Customs_HS_Code: 85332119; Distributor_name: DIGIKEY; Distributor_part_number: 541-1.00KAABCT-ND; Height: 0.28MM; Mfr_name: VISHAY; Mfr_part_number: CRCW02011K00FKED; Mistral Part No: 110015080014-R; Package: 0201; Part_type: RESISTORS\FIXED; Project: OCTASIC_3000; RoHS: RoHS; Temperature: -55°C+155°C; Tolerance: 5%; Voltage: NA; Wattage: 1/20W; Weight: NA; Datasheet: Y:\MIS_DATABASE\DATASHEETS\RESISTORS\CRCW0201.PDF
R346 = RESISTOR: RES 10K 1/16W 1% 0402; Chkd/date: VASANTHA/201216; Crtd /date: GEETHA/290506; Custom_Duty: 15%; Customs_HS_Code: 85332119; Distributor_name: DIGIKEY; Distributor_part_number: 311-10.0KLRTR-ND; Footprint Path: Y:\MIS_DATABASE\Library\ALTIUM_TOOL\PCB_FOOTPRINTS\Altium_Footprint_Lib.PcbLib; Height: 0.40MM; Library Path: Y:\MIS_DATABASE\Library\ALTIUM_TOOL\SCHEMATICS_PARTS\MS_DISCRETE_Library.schlib; Mfr_name: YAGEO AMERICA; Mfr_part_number: RC0402FR-0710KL; Mistral Part No: 110009030220-P; Package: 0402; Part_type: RESISTORS\FIXED; Project: VOCERA; RoHS: Pb-Free; Temperature: -55°C+155°C; Tolerance: 1%; Voltage: NA; Wattage: 1/16W; Weight: 0.65mg; Datasheet: Y:\MIS_DATABASE\DATASHEETS\RESISTORS\YAGEO-RC0402.PDF
R347 R352 R757 = RESISTOR: RES 100K 1/16W 5% 0402; Chkd/date: VASANTHA/061216; Crtd /date: BAVISH/010611; Custom_Duty: 15%; Customs_HS_Code: 85332119; Distributor_name: DIGIKEY; Distributor_part_number: 541-100KJCT-ND; Height: 0.40MM; Mfr_name: VISHAY; Mfr_part_number: CRCW0402100KJNED; Mistral Part No: 110011060002-R; Package: 0402; Part_type: RESISTORS\FIXED; Project: AM4515_EVM_LCD; RoHS: RoHS; Temperature: -55°C+155°C; Tolerance: 5%; Voltage: NA; Wattage: 1/16W; Weight: 0.65mg; Datasheet: Y:\MIS_DATABASE\DATASHEETS\RESISTORS\CRCW0603.PDF
R350 R353 = RESISTOR: RES 47K 1/16W 1% 0402; Chkd/date: VASANTHA/060117; Crtd /date: MAZHAR/141206; Custom_Duty: 15%; Customs_HS_Code: 85332119; Distributor_name: DIGIKEY; Distributor_part_number: 311-47.0KLRCT-ND; Height: 0.40MM; Mfr_name: YAGEO AMERICA; Mfr_part_number: RC0402FR-0747KL; Mistral Part No: 110009030884-R; Package: 0402; Part_type: RESISTORS\FIXED; Project: ADR1B; RoHS: RoHS; Temperature: -55°C+155°C; Tolerance: 1%; Voltage: NA; Wattage: 1/16W; Weight: 0.65mg; Datasheet: Y:\MIS_DATABASE\DATASHEETS\RESISTORS\YAGEO-RC0402.PDF
R351 = RESISTOR: RES 237K 1/16W 1% 0402; Chkd/date: JEBRAN/250815; Crtd /date: JEBRAN/250815; Distributor_name: DIGIKEY; Distributor_part_number: RMCF0402FT237KCT-ND; Height: 0.40MM; Mfr_name: STACKPOLE ELECTRONICS; Mfr_part_number: RMCF0402FT237K; Mistral Part No: 110015080038-R; Package: 0402; Part_type: RESISTORS\FIXED; Project: OCTBTS3600; Temperature: -55°C+155°C; Tolerance: 1%; Voltage: NA; Wattage: 1/16W; Weight: NA; Datasheet: Y:\MIS_DATABASE\DATASHEETS\RESISTORS\RMCF-SERIES1.PDF
R354 = RESISTOR: RES 665K 1/10W 1% 0603; Chkd/date: MANIRAJA/280617; Crtd /date: MANIRAJA/280617; Custom_Duty: 15%; Customs_HS_Code: 85332119; Distributor_name: DIGIKEY; Distributor_part_number: 541-665KHCT-ND; Height: 0.50MM; Mfr_name: VISHAY; Mfr_part_number: CRCW0603665KFKEA; Mistral Part No: 110017060002-R; Package: 0603; Part_type: RESISTORS\FIXED; Project: TI_SVB_CONTROLLER CARD; RoHS: RoHS; Temperature: -55°C+155°C; Tolerance: 1%; Voltage: NA; Wattage: 1/10W; Weight: 2mg; Datasheet: Y:\MIS_DATABASE\DATASHEETS\RESISTORS\CRCW0603.PDF
R362 = RESISTOR: RES 5.62K 1/10W 1% 0603; Chkd/date: USMAN/141113; Crtd /date: USMAN/141113; Custom_Duty: 15%; Customs_HS_Code: 85332119; Distributor_name: DIGIKEY; Distributor_part_number: 541-5.62KHCT-ND; Height: 0.50MM; Mfr_name: VISHAY; Mfr_part_number: CRCW06035K62FKEA; Mistral Part No: 110013110005-R; Package: 0603; Part_type: RESISTORS\FIXED; Project: NPOL_FEP; RoHS: RoHS; Temperature: -55°C+155°C; Tolerance: 1%; Voltage: NA; Wattage: 1/10W; Weight: NA; Datasheet: Y:\MIS_DATABASE\DATASHEETS\RESISTORS\CRCW0603.PDF
SW1 = SW3_B12JV: SWITCH TOGGLE SPDT RT TH; Chkd/date: MANIRAJA/291217; Crtd /date: MANIRAJA/291217; Custom_Duty: 24%; Customs_HS_Code: 85369090; Distributor_name: DIGIKEY; Distributor_part_number: 563-1759-ND; Height: 5.60MM; Mfr_name: NIDEC COPAL; Mistral Part No: 130017120017-R; Package: THRU-HOLE; Part_type: ELECTRO-MECHANICAL\SWITCH; Project: TI_MAXIE_CPB; RoHS: RoHS; Temperature: -20°C+85°C; Tolerance: NA; Voltage: NA; Wattage: NA; Weight: NA; Datasheet: Y:\MIS_DATABASE\DATASHEETS\MISC\SWITCHES\ATE-SER.PDF
TP2 TP4 TP6 TP21 TP87 TP88 = TESTPOINT: ACCESSORIE PC TEST POINT; Chkd/date: VASANTHA/121216; Crtd /date: MANIRAJA/121216; Distributor_name: DIGIKEY; Distributor_part_number: 36-5002-ND; Height: 4.57MM; Mfr_name: KEYSTONE; Mistral Part No: 160016120008-R; Package: NA; Part_type: ACCESSORIES; Project: EPOS_EVM; RoHS: RoHS; Temperature: NA; Tolerance: NA; Voltage: NA; Wattage: NA; Weight: NA; Datasheet: Y:\MIS_DATABASE\DATASHEETS\MISC\ACCESSORIES\5002.PDF
TP9 TP10 = TESTPOINT: TESTPOINT 1.0MM DRILL PTH; Chkd/date: MAZHAR/271211; Crtd /date: SHREESHAIL/041005; Distributor_name: NA; Distributor_part_number: NA; Height: NA; Mfr_name: LOCAL; Mistral Part No: 130009030938; Package: THRU-HOLE; Part_type: MISC\TESTPOINT; Project: HSE; Datasheet: NA
TP89 TP92 = TESTPOINT: TESTPOINT CIR 40 SMD; Chkd/date: MAZHAR/190505; Crtd /date: MAZHAR/190505; Distributor_name: NA; Distributor_part_number: NA; Footprint Path: Y:\MIS_DATABASE\Library\ALTIUM_TOOL\PCB_FOOTPRINTS\Altium_Footprint_Lib.PcbLib; Height: NA; Library Path: Y:\MIS_DATABASE\Library\ALTIUM_TOOL\SCHEMATICS_PARTS\MS_DISCRETE_Library.schlib; MECHANICAL 3D STEP FILE: NA; Mfr_name: LOCAL; Mistral Part No: 130009030933; Package: SMD; Project: RAINIER-3; RoHS: NA; Temperature: NA; Tolerance: NA; Voltage: NA; Wattage: NA; Weight: NA; Datasheet: NA
U62 = MIC5060YML_MLF8: IC ULTRA SMALL HIGH SIDE MOSFET DRIVER MLF8; Chkd/date: MANIRAJA/131017; Crtd /date: MANIRAJA/131017; Custom_Duty: 15%; Customs_HS_Code: 85423100; Distributor_name: DIGIKEY; Distributor_part_number: 576-3669-1-ND; Height: 1.00MM; Mfr_name: MICREL; Mfr_part_number: MIC5060YML-TR; Mistral Part No: 142017100011-R; Package: MLF8; Part_type: ICS\POWER\DRIVER; Project: TI_MAXIE_CPB; RoHS: RoHS; Temperature: -40°C+85°C; Tolerance: NA; Voltage: NA; Wattage: NA; Weight: NA; Datasheet: Y:\MIS_DATABASE\DATASHEETS\ICS\POWER\MIC5060YML.PDF
U66 = LM5060_MSOP10: IC CONTROLLER HIGH-SIDE PROTECTION VSSOP10; Chkd/date: VASANTHA/101015; Crtd /date: VASANTHA/101015; Custom_Duty: 15%; Customs_HS_Code: 85423100; Distributor_name: DIGIKEY; Distributor_part_number: 296-39024-1-ND; Height: 1.10MM; Mfr_name: TEXAS INSTRUMENTS; Mfr_part_number: LM5060MM/NOPB; Mistral Part No: 142015100007-R; Package: VSSOP10; Part_type: ICS\POWER\MANAGEMENT; Project: GALILEO_EVM; RoHS: RoHS; Temperature: -40°C+125°C; Tolerance: NA; Voltage: NA; Wattage: NA; Weight: NA; Datasheet: Y:\MIS_DATABASE\DATASHEETS\ICS\POWER\LM5060-TI.PDF
U119 = TPS62177_WSON10: IC 3.3V 0.5A STEP DOWN CONVERTER WITH SLEEP MODE WSON10; Chkd/date: MANIRAJA/170719; Crtd /date: MANIRAJA/170719; Custom_Duty: 15%; Customs_HS_Code: 85423100; Distributor_name: DIGIKEY; Distributor_part_number: 296-41856-1-ND; Footprint Path: Y:\MIS_DATABASE\Library\ALTIUM_TOOL\PCB_FOOTPRINTS\Altium_Footprint_Lib.PcbLib; Height: 0.80MM; Library Path: Y:\MIS_DATABASE\Library\ALTIUM_TOOL\SCHEMATICS_PARTS\MS_MISCPOWER_Library.schlib; Mfr_name: TEXAS INSTRUMENTS; Mistral Part No: 142019070007-R; Package: WSON10; Part_type: ICS\POWER\DC-DC CONVERTER; Project: TI_MAXIE_CPB; RoHS: RoHS; Temperature: -40°C+85°C; Tolerance: NA; Voltage: NA; Wattage: NA; Weight: 15mg; Datasheet: Y:\MIS_DATABASE\DATASHEETS\ICS\POWER\TPS62177.PDF

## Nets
DGND: C39.2 C72.2 C245.1 C246.1 C247.1 C248.1 C254.2 C281.2 C282.2 C291.2 C333.2 C336.2 C619.2 C627.2 C628.2 C630.2 C638.2 C639.2 C640.2 C641.2 C656.2 C663.2 C664.2 C666.1 C670.1 C671.2 C675.1 C676.1 C677.2 C700.2 C706.2 D1.2(A) D2.2(ANODE) D14.2(ANODE) FL7.2 J1.2 J1.3 J2.3 J2.4 J2.5 J2.6 J2.7 J9.3 J22.12 J22.16 J22.24 J22.41(GND1) J22.42(GND2) J22.43(GND3) J22.44(GND4) J35.12 J35.17 J35.22 J35.30 J35.35 J35.36 J35.121 J35.122 J35.123 J35.124 J35.125 J35.126 J35.127 J35.128 J36.12 J36.17 J36.22 J36.30 J36.35 J36.36 J36.61 J36.62 J36.63 J36.64 J39.6 J39.7 J39.10 J39.13 J39.16 J39.19 J39.22 J39.29 J39.33 J39.34 J39.SH1 J39.SH2 J39.SH3 J39.SH4 LD5.1 Q8.2(S) R350.2 R353.2 R676.1 R679.1 SW1.1 SW1.SH1 SW1.SH2 TP2.1(TP) TP4.1(TP) TP6.1(TP) TP21.1(TP) TP87.1(TP) TP88.1(TP) U62.4(GND) U62.9(EP) U66.6(GND) U100.11(GND) U100.21(PAD) U108.3(GND) U111.11(GND) U111.21(PAD) U112.2(GND) U114.2(GND) U119.1(PGND) U119.5(FB) U119.6(AGND) U119.11(EP) ; also on sheet 11 12 13 14 15 16 17 18 19 20 21 22 23 24 25 26 27 28 29 30 31 32 33 34 35 36 37 38 39 40 41 42
VCC1V8: C246.2 C248.2 C619.1 C639.1 C641.1 C675.2 C676.2 C677.1 J22.38 J22.40 J35.2 J35.4 J36.2 J36.4 J37.1 J39.4 J39.5 R624.2 R700.1 U100.2(VCCA) U114.4(VCC) ; also on sheet 11 18 19 20 21 22 23 26 29 31 33 35 36 37 38 41
VCC3V3_IO: C245.2 C247.2 C627.1 C638.1 C640.1 C664.1 C666.2 C670.2 C671.1 J22.30 J22.32 J22.34 J22.36 J35.56 J35.58 J35.60 J36.56 J36.58 J36.60 J37.3 J39.1 J39.2 J39.3 J46.3 R658.2 R671.1 U100.19(VCCB) U111.19(VCCB) U112.4(VCC) ; also on sheet 11 18 19 20 21 22 23 24 25 26 28 29 30 31 33 34 35 36 37 38 39 41 42
VCC3V3_TA: J46.2 ; also on sheet 24 25
VCC3V3_TA_OPT: C706.1 J46.1 L12.2 R757.2 TP89.1(TP) U119.8(SLEEP) U119.10(VOS)
VCC_5V0: C628.1 C630.1 J35.55 J35.57 J35.59 J36.55 J36.57 J36.59 ; also on sheet 30 33 35 40
VCC_12V0: C336.1 J9.2 ; also on sheet 35 40
VCC_HDR: C656.1 C663.1 J37.2 R662.1 R664.2 R666.1 U108.5(VCC) U111.2(VCCA)
VIN: C254.1 D6.3(K) Q1.4(D) R337.1 U62.1(V+)
VINPUT: C39.1 C282.1 C700.1 Q1.3(S) Q2.4(D) R13.1 R347.2 R351.1 R352.1 R354.1 R362.1 R767.1 TP10.1(TP) U62.3(SOURCE) U66.2(VIN) U119.2(VIN)
BOARDID_HDMI_A0: J35.8 J36.8
BOARDID_HDMI_A1: J35.10 J36.10
CON_LCD_PWR_DN: J35.40 J36.40 ; also on sheet 37
CSI0_RXN0: J22.7 J39.9 U34.G28(CSI0_RXN0)
CSI0_RXN1: J22.11 J39.12 U34.H27(CSI0_RXN1)
CSI0_RXN2: J22.15 J39.15 U34.F26(CSI0_RXN2)
CSI0_RXN3: J22.19 J39.18 U34.H25(CSI0_RXN3)
CSI0_RXN4: J22.23 J39.21 U34.G24(CSI0_RXN4)
CSI0_RXP0: J22.5 J39.8 U34.F28(CSI0_RXP0)
CSI0_RXP1: J22.9 J39.11 U34.G27(CSI0_RXP1)
CSI0_RXP2: J22.13 J39.14 U34.G26(CSI0_RXP2)
CSI0_RXP3: J22.17 J39.17 U34.G25(CSI0_RXP3)
CSI0_RXP4: J22.21 J39.20 U34.F24(CSI0_RXP4)
CSI_`MCU_SPI0_D0: J22.18 J39.30 U111.4(A3)
CSI_MCU_SCL: J22.2 J39.25 R662.2 U111.1(A1)
CSI_MCU_SDA: J22.4 J39.24 R666.2 U111.3(A2)
CSI_MCU_SPI0_CLK: J22.20 J39.31 U111.5(A4)
CSI_MCU_SPI0_CS0: J22.22 J39.32 U111.6(A5)
CSI_REF_CLK: J22.10 U111.8(A7)
CSI_REF_CLK_1V8: J39.26 R699.2
CSI_REF_CLK_3V3: R674.2 U111.13(B7)
CSI_RSTn: J22.14 J39.23 R664.1 U108.4(Y) U111.10(OE)
GATE: C291.1 Q2.1(G) U66.10(GATE)
GP1_TOUCH_EVT: J35.38 J36.38 ; also on sheet 37
GPIO_CSI_RESETn: R658.1 U108.1(A) ; also on sheet 37
HDMI_GPMC_BRD_DET: J35.18 J36.18 ; also on sheet 20
MAIN: F1.1 J1.1 J2.1 J2.2
MCASP1_ACLKR: U100.7(A6) ; also on sheet 33
MCASP1_ACLKR_3V3: J35.115 U100.14(B6)
MCASP1_ACLKX: U100.4(A3) ; also on sheet 33
MCASP1_ACLKX_3V3: J35.109 U100.17(B3)
MCASP1_AFSR: U100.8(A7) ; also on sheet 33
MCASP1_AFSR_3V3: J35.117 U100.13(B7)
MCASP1_AFSX: U100.1(A1) ; also on sheet 33
MCASP1_AFSX_3V3: J35.105 U100.20(B1)
MCASP1_AHCLKR: U100.9(A8) ; also on sheet 33
MCASP1_AHCLKR_3V3: J35.119 U100.12(B8)
MCASP1_AHCLKX: U100.5(A4) ; also on sheet 33
MCASP1_AHCLKX_3V3: J35.111 U100.16(B4)
MCASP1_AXR0: U100.6(A5) ; also on sheet 33
MCASP1_AXR0_3V3: J35.113 U100.15(B5)
MCASP1_AXR1: U100.3(A2) ; also on sheet 33
MCASP1_AXR1_3V3: J35.107 U100.18(B2)
MCU_SPI0_CLK: U111.16(B4) ; also on sheet 34
MCU_SPI0_CS0: U111.15(B5) ; also on sheet 34
MCU_SPI0_D0/BOOTMODE7: U111.17(B3) ; also on sheet 25 34
MIC-GATE: Q1.1(G) R338.1
PGD: R346.1 R347.1 U66.8(NPGD)
PORz_OUT: J35.16 J36.16 U108.2(B) ; also on sheet 19 21 25 33 34 35
R_SOC_SPI1_CS1: J35.42 J36.42 R311.2
SHIELD: FL7.1 J2.SH1 J2.SH2 J2.SH3 J2.SH4
SoC_I2C2_SCL: U34.T27(GPMC0_CSN3) ; also on sheet 20 24 26
SoC_I2C2_SDA: U34.R25(GPMC0_CSN2) ; also on sheet 20 24 26
SOC_MCU_SCL: J35.32 J36.32 U111.20(B1) ; also on sheet 20 34 35
SOC_MCU_SDA: J35.34 J36.34 U111.18(B2) ; also on sheet 20 34 35
SOC_SPI1_CLK: J35.48 J36.48 ; also on sheet 34 35 38
SOC_SPI1_CS1: R311.1 ; also on sheet 34 38
SOC_SPI1_MISO: J35.46 J36.46 ; also on sheet 34 35 38
SOC_SPI1_MOSI: J35.44 J36.44 ; also on sheet 34 35 38
SOC_WKUP_SCL: J35.6 J36.6 ; also on sheet 20 33 34 35 41
SOC_WKUP_SDA: J35.14 J36.14 ; also on sheet 20 33 34 35 41
TEST_POWERDOWN: R352.2 U66.5(EN) ; also on sheet 24
TIMER_IO2: RA6.1 ; also on sheet 38
TIMER_IO3: RA6.2 ; also on sheet 38
TIMER_IO6: RA6.3 ; also on sheet 38
TIMER_IO7: RA6.4 ; also on sheet 38
USB1_HDMI_GPMC_DM: J35.52 J36.52 ; also on sheet 30
USB1_HDMI_GPMC_DP: J35.54 J36.54 ; also on sheet 30
USB1_HDMI_GPMC_DRVBUS: J35.50 J36.50 ; also on sheet 30
VMAIN: C72.1 C333.1 Q2.3(S) R9.1 R359.1 TP9.1(TP) ; also on sheet 39 40 42
VOUT1_DATA20: J35.7 J36.7 U34.T28(GPMC0_BE0N_CLE)
VOUT1_DATA21: RA6.8 RA17.5 U34.P23(GPMC0_BE1N)
VOUT1_DATA21_TEST_HDR: J35.5 J36.5 RA17.4
VOUT1_DATA22: J35.3 J36.3 U34.R26(GPMC0_WAIT0)
VOUT1_DATA23: RA6.7 RA17.6 U34.R23(GPMC0_WAIT1)
VOUT1_DATA23_TEST_HDR: J35.1 J36.1 RA17.3
VOUT1_DE: RA6.5 RA17.8 U34.T23(GPMC0_CSN1)
VOUT1_DE_TEST_HDR: J35.28 J36.28 RA17.1
VOUT1_HSYNC: RA6.6 RA17.7 U34.T24(GPMC0_DIR)
VOUT1_HSYNC_TEST_HDR: J35.26 J36.26 RA17.2
VOUT1_PCLK: J35.20 J36.20 U34.R24(GPMC0_CSN0)
VOUT1_VSYNC: J35.24 J36.24 U34.T25(GPMC0_WPN)
VOUT_D0_BOOTMODE0: J35.51 J36.51 U34.M27(GPMC0_AD0) ; also on sheet 25
VOUT_D1_BOOTMODE1: J35.49 J36.49 U34.M23(GPMC0_AD1) ; also on sheet 25
VOUT_D2_BOOTMODE2: J35.47 J36.47 U34.M28(GPMC0_AD2) ; also on sheet 25
VOUT_D3_BOOTMODE3: J35.45 J36.45 U34.M24(GPMC0_AD3) ; also on sheet 25
VOUT_D4_BOOTMODE4: J35.43 J36.43 U34.N24(GPMC0_AD4) ; also on sheet 25
VOUT_D5_BOOTMODE5: J35.41 J36.41 U34.N27(GPMC0_AD5) ; also on sheet 25
VOUT_D6_BOOTMODE6: J35.39 J36.39 U34.N28(GPMC0_AD6) ; also on sheet 25
VOUT_D7_BOOTMODE7: J35.37 J36.37 U34.M25(GPMC0_AD7) ; also on sheet 25
VOUT_D8_BOOTMODE8: J35.33 J36.33 U34.N23(GPMC0_AD8) ; also on sheet 25
VOUT_D9_BOOTMODE9: J35.31 J36.31 U34.M26(GPMC0_AD9) ; also on sheet 25
VOUT_D10_BOOTMODE10: J35.29 J36.29 U34.P28(GPMC0_AD10) ; also on sheet 25
VOUT_D11_BOOTMODE11: J35.27 J36.27 U34.P27(GPMC0_AD11) ; also on sheet 25
VOUT_D12_BOOTMODE12: J35.25 J36.25 U34.N26(GPMC0_AD12) ; also on sheet 25
VOUT_D13_BOOTMODE13: J35.23 J36.23 U34.N25(GPMC0_AD13) ; also on sheet 25
VOUT_D14_BOOTMODE14: J35.21 J36.21 U34.P24(GPMC0_AD14) ; also on sheet 25
VOUT_D15_BOOTMODE15: J35.19 J36.19 U34.R27(GPMC0_AD15) ; also on sheet 25
VOUT_D16: J35.15 J36.15 U34.R28(GPMC0_CLK)
VOUT_D17_BOOTMODE16: J35.13 J36.13 U34.P25(GPMC0_ADVN_ALE) ; also on sheet 25
VOUT_D18_BOOTMODE17: J35.11 J36.11 U34.P26(GPMC0_OEN_REN) ; also on sheet 25
VOUT_D19_BOOTMODE18: J35.9 J36.9 U34.U28(GPMC0_WEN) ; also on sheet 25
N16818481: LD6.1 Q8.3(D)
N16818579: D14.1(CATHODE) Q8.1(G) R346.2
N16818604: R362.2 U66.1(SENSE)
N16818646: LD6.2 R13.2
N16818667: R359.2 U66.9(OUT)
N16818684: C281.1 U66.7(TIMER)
N16818713: LD5.2 R9.2
N16818872: R350.1 R351.2 U66.4(UVLO)
N16818874: R353.1 R354.2 U66.3(OVP)
N17309165: R676.2 U111.9(A8)
N17314921: R679.2 U111.12(B8)
N17402100: R624.1 U100.10(OE)
N18001847: R700.2 U114.1(ENABLE/DISABLE)
N18001866: R699.1 U114.3(OUTPUT)
N18289892: R674.1 U112.3(OUTPUT)
N18289915: R671.2 U112.1(ENABLE/DISABLE)
N18546005: D2.1(CATHODE) D6.1(A1) D6.2(A2) F1.2 R5.1
N18546027: LD1.1 R5.2
N18546044: D1.1(K) LD1.2
N18547174: R338.2 U62.5(GATE)
N18547348: R337.2 SW1.2 U62.2(I/P)
N23728299: L12.1 U119.9(SW)
N23729329: R757.1 TP92.1(TP) U119.7(PG)
N23730398: R767.2 U119.3(EN)

Not connected (* = marked no-connect by the designer): J9 1*; J22 1* 3* 6* 8* 25* 26* 27* 28* 29* 31* 33* 35* 37* 39*; J35 53* 61 62 63 64 65 66 67 68 69 70 71 72 73 74 75 76 77 78 79 80 81 82 83 84 85 86 87 88 89 90 91 92 93 94 95 96 97 98 99 100 101 102 103 104 106 108 110 112 114 116 118 120; J36 53; J39 27* 28* 35* 36*; SW1 3*; U62 6(NC1)* 7(NC2)* 8(NC3)*; U111 7(A6)* 14(B6)*; U119 4(NC)*

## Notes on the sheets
sheet 43
- OVER VOLTAGE PROTECTION CIRCUIT
- VCC = 11V-28V
  ICC max = 5A
- Cooling FAN Header
- RED
- VCC = 11V-28V
  ICC max = 10A
- ON/ OFF Control SWITCH
- Note:-
- UVLO set for 11V
  OVP set for 28V
- Condition
- LED Status(LD1)
- Reverse Voltage
- ON
- Fault Indication
- TEST AUTOMATION BOARD POWER
- RED
- Condition
- LED Status(LD6)
- VINPUT between 11 to 28V
- OFF
- VINPUT above 28V or below 11V
- ON
- Note:-
- When fault is indicated, set to proper voltage and power cycle the board.
- Ground test points
sheet 44
- CSI INTERFACE
- Jumper to select the IO level  of CSI Control interfaces
  (I2C & SPI)
- CSI RESET
- DSS/GPMC Interface
- 0- Ohm Res MUX between HDMI / GPMC and Test Header Timer signals.
  -For  HDMI / GPMC  ,  RA17 Should be installed and  RA6 Should be DNI'd.
  -For test header Timer signals , RA6  Should be Installed and  RA17  Should be
  DNI'd.
  Customer Note – See Users Guide for more information on DNI resistor alternatives
